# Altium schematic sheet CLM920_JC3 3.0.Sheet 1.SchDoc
size 431 x 279 mm
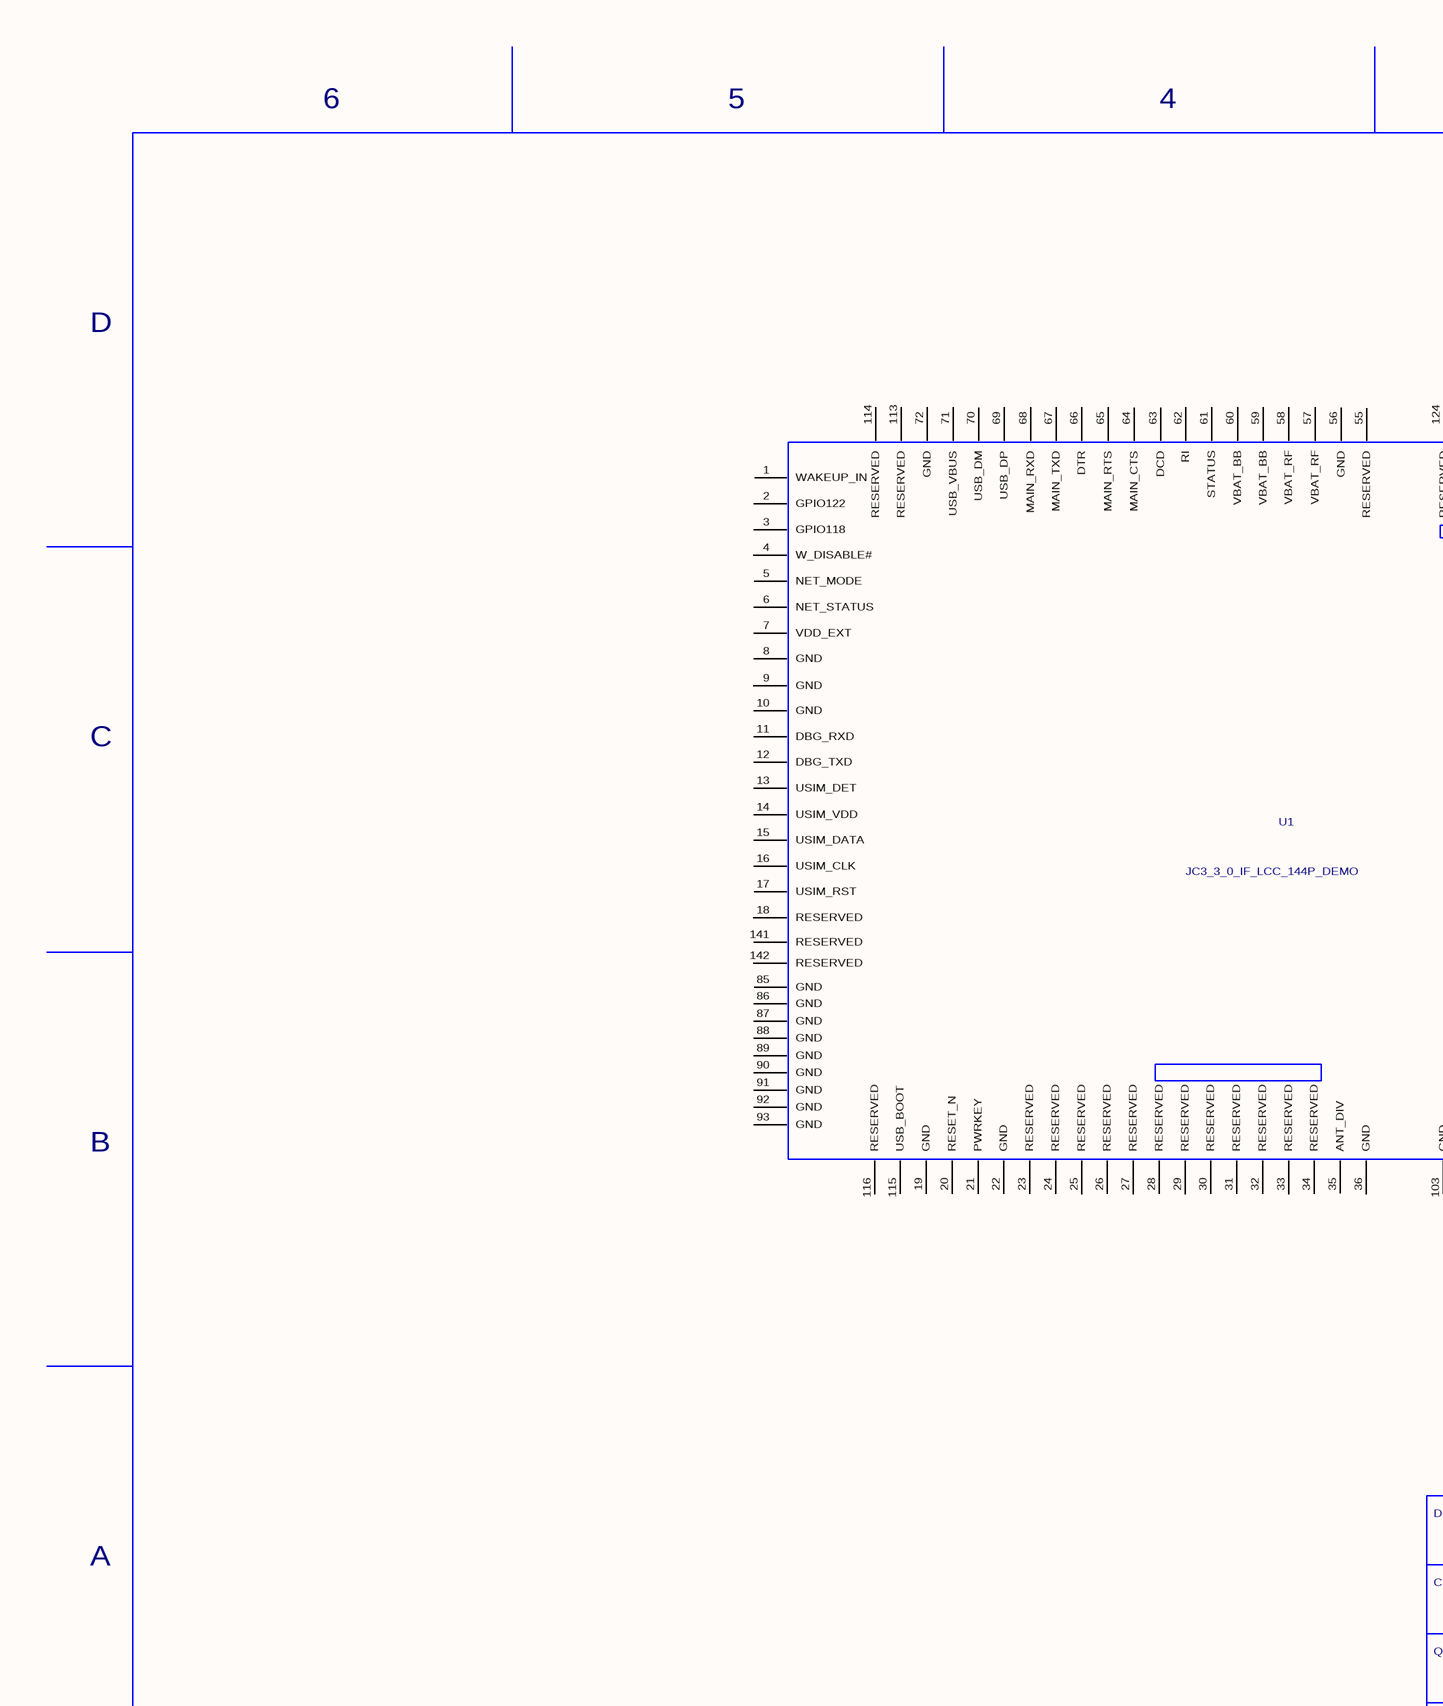
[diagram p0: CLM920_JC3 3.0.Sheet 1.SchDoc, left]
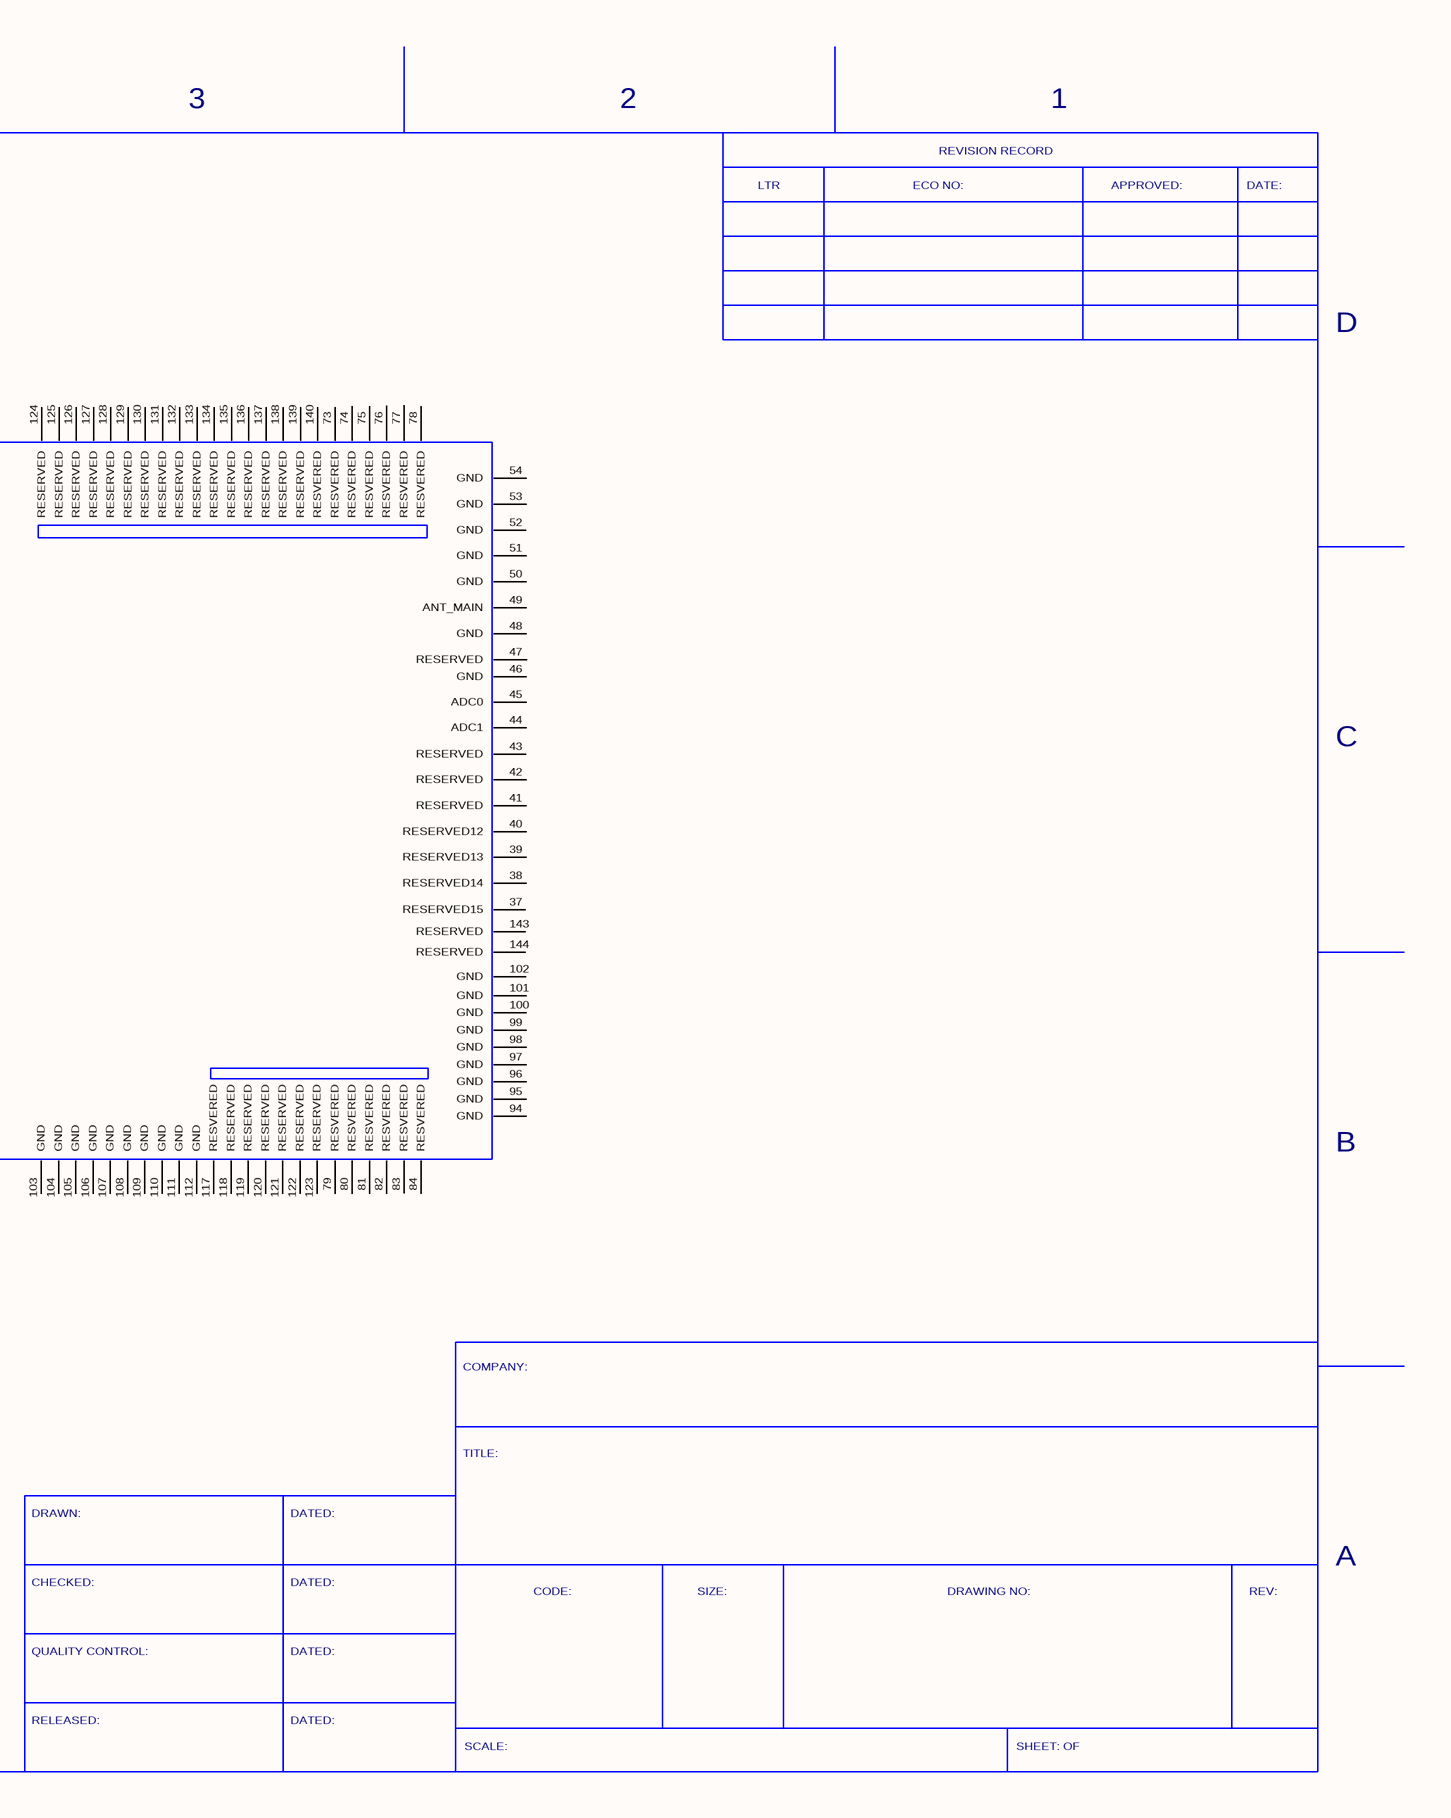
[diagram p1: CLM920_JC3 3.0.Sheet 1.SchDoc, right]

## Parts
U1  JC3_3_0_IF_LCC_144P_DEMO  [IF_LCC_144P_DEMO]

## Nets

Not connected (* = marked no-connect by the designer): U1 1(WAKEUP_IN) 2(GPIO122) 3(GPIO118) 4(W_DISABLE#) 5(NET_MODE) 6(NET_STATUS) 7(VDD_EXT) 8(GND) 9(GND) 10(GND) 11(DBG_RXD) 12(DBG_TXD) 13(USIM_DET) 14(USIM_VDD) 15(USIM_DATA) 16(USIM_CLK) 17(USIM_RST) 18(RESERVED) 19(GND) 20(RESET_N) 21(PWRKEY) 22(GND) 23(RESERVED) 24(RESERVED) 25(RESERVED) 26(RESERVED) 27(RESERVED) 28(RESERVED) 29(RESERVED) 30(RESERVED) 31(RESERVED) 32(RESERVED) 33(RESERVED) 34(RESERVED) 35(ANT_DIV) 36(GND) 37(RESERVED15) 38(RESERVED14) 39(RESERVED13) 40(RESERVED12) 41(RESERVED) 42(RESERVED) 43(RESERVED) 44(ADC1) 45(ADC0) 46(GND) 47(RESERVED) 48(GND) 49(ANT_MAIN) 50(GND) 51(GND) 52(GND) 53(GND) 54(GND) 55(RESERVED) 56(GND) 57(VBAT_RF) 58(VBAT_RF) 59(VBAT_BB) 60(VBAT_BB) 61(STATUS) 62(RI) 63(DCD) 64(MAIN_CTS) 65(MAIN_RTS) 66(DTR) 67(MAIN_TXD) 68(MAIN_RXD) 69(USB_DP) 70(USB_DM) 71(USB_VBUS) 72(GND) 73(RESVERED) 74(RESVERED) 75(RESVERED) 76(RESVERED) 77(RESVERED) 78(RESVERED) 79(RESVERED) 80(RESVERED) 81(RESVERED) 82(RESVERED) 83(RESVERED) 84(RESVERED) 85(GND) 86(GND) 87(GND) 88(GND) 89(GND) 90(GND) 91(GND) 92(GND) 93(GND) 94(GND) 95(GND) 96(GND) 97(GND) 98(GND) 99(GND) 100(GND) 101(GND) 102(GND) 103(GND) 104(GND) 105(GND) 106(GND) 107(GND) 108(GND) 109(GND) 110(GND) 111(GND) 112(GND) 113(RESERVED) 114(RESERVED) 115(USB_BOOT) 116(RESERVED) 117(RESVERED) 118(RESERVED) 119(RESERVED) 120(RESERVED) 121(RESERVED) 122(RESERVED) 123(RESERVED) 124(RESERVED) 125(RESERVED) 126(RESERVED) 127(RESERVED) 128(RESERVED) 129(RESERVED) 130(RESERVED) 131(RESERVED) 132(RESERVED) 133(RESERVED) 134(RESERVED) 135(RESERVED) 136(RESERVED) 137(RESERVED) 138(RESERVED) 139(RESERVED) 140(RESVERED) 141(RESERVED) 142(RESERVED) 143(RESERVED) 144(RESERVED)

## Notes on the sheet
- 6
- 5
- 4
- 3
- 2
- REVISION RECORD
- 1
- LTR
- ECO NO:
- APPROVED:
- DATE:
- D
- C
- B
- COMPANY:
- TITLE:
- DRAWN:
- DATED:
- A
- CHECKED:
- CODE:
- SIZE:
- DRAWING NO:
- REV:
- QUALITY CONTROL:
- RELEASED:
- SCALE:
- SHEET: OF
